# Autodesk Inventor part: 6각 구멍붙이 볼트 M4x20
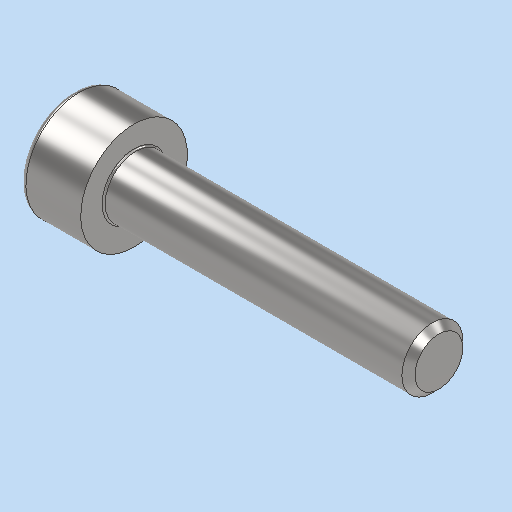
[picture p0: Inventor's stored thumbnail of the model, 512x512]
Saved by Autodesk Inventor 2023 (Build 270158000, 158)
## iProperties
Created: 2026-04
Part Number: 6각 구멍붙이 볼트 M4x20
Material: 강철, 연강
Description: 6각머리 태핑 나사
Document SubType Name: Modeling
Designer: home
Density: 7.85 g/cm^3
Appearance: 기본값
Author: jhkim
Sending System: Autodesk Inventor 2027
Preprocessor: ST-DEVELOPER v20.1
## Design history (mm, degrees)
feature "Solid1"
node "솔리드1"
